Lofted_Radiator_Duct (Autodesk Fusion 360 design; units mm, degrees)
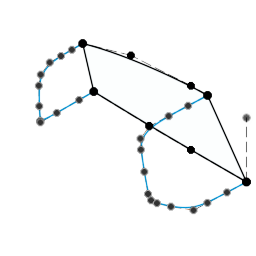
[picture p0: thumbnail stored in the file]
part number: 2026-08-31-12-37-40-158
sketch "Sketch1" plane through (0, 0, 0) normal (0, 1, 0) x axis (1, 0, 0)
  line L1 (0, -100) -> (0, 0)
  line L2 (-70.0208, -100) -> (0, 0)
  curve K1 (-100.0208, -100) -> (-70.0208, -100)
  curve K2 (-208.0646, -93.3918) -> (-100.0208, -100)
  curve K3 (-294.8725, -68.5) -> (-208.0646, -93.3918)
  curve K4 (-294.8725, -68.5) -> (-70.0208, -100)
  curve K5 (-100, 0) -> (0, 0)
  curve K6 (-175, 0) -> (-100, 0)
  curve K7 (-275, -3.5) -> (-175, 0)
  curve K8 (-275, -3.5) -> (0, 0)
  line L3 (-294.8725, -68.5) -> (-275, -3.5)
  point P1 (0, 0)
  point P2 (0, 0)
  point P3 (0, -100)
  point P4 (-70.0208, -100)
  point P10 (-275, -3.5)
  point P7 (-294.8725, -68.5)
  point P8 (-100, 0)
  point P9 (-175, 0)
  point P5 (-100.0208, -100)
  coincident P1 P2
  vertical L1
  horizontal P3 P4
  collinear K5 K6
  horizontal K1
  horizontal K5
  dimension "d1" distance P2 P3 = 100
  dimension "d2" angle L1 L2 = 35
  dimension "d3" distance P2 P10 = 3.5
  dimension "d4" angle L2 L3 = 18
  dimension "d5" distance P7 P10 = 65
  dimension "d6" distance P2 P10 = 275
  dimension "d7" distance P2 P8 = 100
  dimension "d8" distance P8 P9 = 75
  dimension "d9" distance P4 P5 = 30
  dimension "d10" angle K1 K2 = 3.5
  dimension "d11" angle K2 K3 = 12.5
work_plane "WorkPlane1" RotateAngle 80 ExtraOffset 0
sketch "Sketch2" plane through (0, 0, 0) normal (-0.8067, 0.1736, -0.5649) x axis (-0.5736, 0, 0.8192)
  curve K1 (122.0775, -31.091) -> (122.0775, 0)
  curve K2 (122.0775, -62.1821) -> (122.0775, -31.091)
  curve K3 (122.0775, -93.2731) -> (122.0775, -62.1821)
  curve K4 (113.6278, -111.4326) -> (122.0775, -93.2731)
  curve K5 (100.8232, -117.3608) -> (113.6278, -111.4326)
  curve K6 (73.5899, -125.676) -> (100.8232, -117.3608)
  curve K7 (46.1541, -133.7331) -> (73.5899, -125.676)
  curve K8 (37.0684, -133.5725) -> (46.1541, -133.7331)
  curve K9 (30.2304, -127.6943) -> (37.0684, -133.5725)
  curve K10 (17.8528, -111.5942) -> (30.2304, -127.6943)
  curve K11 (0, -84.5744) -> (17.8528, -111.5942)
  curve K12 (0, -62.4154) -> (0, -84.5744)
  curve K13 (0, -31.2077) -> (0, -62.4154)
  curve K14 (0, 0) -> (0, -31.2077)
  curve K15 (0, 0) -> (122.0775, 0)
  point P2 (122.0775, 0)
  point P4 (122.0775, 0)
  point P3 (0, 0)
  point P18 (0, 0)
  coincident P2 P4
  coincident P3 P18
  collinear K13 K14
  collinear K12 K13
  collinear K1 K2
  collinear K2 K3
  equal K1 K2
  equal K2 K3
  equal K13 K14
  vertical K1
  vertical K14
work_plane "WorkPlane2" RotateAngle 90 ExtraOffset 0
sketch "Sketch3" plane through (-250.5141, 0, -76.5898) normal (-0.9563, 0, -0.2924) x axis (-0.2924, 0, 0.9563)
  curve K1 (151.7192, -19.4887) -> (151.7192, 0)
  curve K2 (151.7192, -39.1013) -> (151.7192, -19.4887)
  curve K3 (151.7192, -59.3294) -> (151.7192, -39.1013)
  curve K4 (143.0783, -78.0575) -> (151.7192, -59.3294)
  curve K5 (130.6512, -85.1305) -> (143.0783, -78.0575)
  curve K6 (104.7397, -91.9297) -> (130.6512, -85.1305)
  curve K7 (85.8177, -95.6912) -> (104.7397, -91.9297)
  curve K8 (83.7493, -95.9808) -> (85.8177, -95.6912)
  curve K9 (83.7493, -66.5154) -> (83.7493, -95.9808)
  curve K10 (83.7493, -26.1348) -> (83.7493, -66.5154)
  curve K11 (83.7493, 0) -> (83.7493, -26.1348)
  curve K12 (83.7493, 0) -> (151.7192, 0)
  point P2 (151.7192, 0)
  point P4 (151.7192, 0)
  point P3 (83.7493, 0)
  point P15 (83.7493, 0)
  coincident P2 P4
  coincident P3 P15
  vertical K11
  vertical K1
  collinear K10 K11
  collinear K9 K10
  collinear K1 K2
  collinear K2 K3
